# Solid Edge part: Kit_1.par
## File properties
Sűrűség: 0,000 kg/m^3
Pontosság: 0,990
Author: bmolnar
Last saved by: bmolnar
Revision: 77
Username: bmolnar
Dokumentum tartalom típus: 0
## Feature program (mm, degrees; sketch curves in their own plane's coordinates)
base feature "unnamed BaseFeature 1"
sketch for "Furat_1" plane through (-18.15, 18.15, 0) normal (1, 0, 0) x-axis (0, 0, -1)
  hole centre (0, -13.85) bore radius 2.067
hole "Furat_1" nominal diameter 5 finite  StartChamferOffset = 0.6 mm; StartChamferAngle = 45 deg
sketch for "Furat_2" plane through (-11, 6.7, 11) normal (0, 1, 0) x-axis (0, 0, -1)
  hole centre (0, 0) bore radius 2.067
hole "Furat_2" nominal diameter 5
sketch for "unnamed Hole 1" plane through (-11, 6.7, 11) normal (0, 1, 0) x-axis (0, 0, -1)
  hole centre (22, 0) bore radius 2.067
hole "unnamed Hole 1"
sketch for "unnamed Hole 2" plane through (-11, 6.7, 11) normal (0, 1, 0) x-axis (0, 0, -1)
  hole centre (22, -22) bore radius 2.067
hole "unnamed Hole 2"
sketch for "unnamed Hole 3" plane through (-11, 6.7, 11) normal (0, 1, 0) x-axis (0, 0, -1)
  hole centre (0, -22) bore radius 2.067
hole "unnamed Hole 3"
pattern "unnamed Pattern 1" of "Furat_2", "unnamed Hole 1", "unnamed Hole 2", "unnamed Hole 3"
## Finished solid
Body 1: solid body, 238 faces, 596 edges, 372 vertices, 2 internal voids.
  Faces by surface: plane 121, cylinder 54, swept 43, cone 16, torus 4
  Edges by curve: line 361, circle 135, spline 90, curve on surface 5, intersection 4, ellipse 1
Bounding box of the edges (mm; curved faces can reach further): 36.300 x 11.800 x 36.300, from (-18.15, 0, -18.15) to (18.15, 11.8, 18.15).
Cylindrical faces by radius (mm): R0.2 x18, R0.4246 x1, R0.4865 x1, R2.067 x5, R3.75 x2, R4 x4, R4.1 x12, R4.5 x1, R5.45 x2, R5.55 x2, R11.25 x6
Conical faces (half-angle, radius in mm at the cone's reference point): 0.5 deg R4.5 x4, 45 deg R2.317 x2, 45 deg R2.367 x2, 45 deg R2.667 x1, 45 deg R4.25 x2, 45 deg R4.65 x1, 45 deg R5.3 x2, 45 deg R5.35 x2
Toroidal faces (ring radius, tube radius in mm): R3.8 r0.2 x2, R4.4 r0.4 x2
Planar faces by outward normal: +x 5, +y 14, +z 13, -x 7, -y 3, -z 15, oblique 64
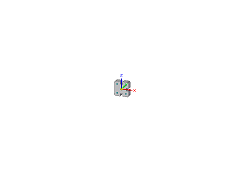
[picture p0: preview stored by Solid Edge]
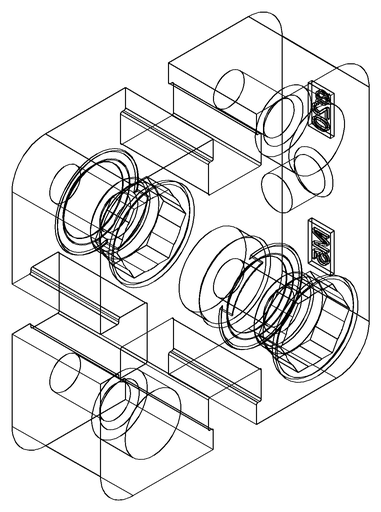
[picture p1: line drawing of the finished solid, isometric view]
